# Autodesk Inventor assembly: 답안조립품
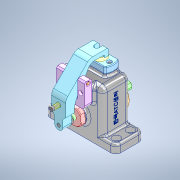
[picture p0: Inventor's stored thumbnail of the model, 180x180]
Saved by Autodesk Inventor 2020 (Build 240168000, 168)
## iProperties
Created: 2023-12
Part Number: 답안조립품
Document SubType Name: Assembly
Designer: oem
Author: oem
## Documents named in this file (14)
- C:\Users\oem\Desktop\731208V1015\답안조립품.iam
- C:\Users\oem\Desktop\731208V1015\본체.ipt
- C:\Users\oem\Desktop\731208V1015\가이드 부시.ipt
- C:\Users\oem\Desktop\731208V1015\조절 부시.ipt
- C:\Users\oem\Desktop\731208V1015\클램프 샤프트.ipt
- C:\Users\oem\Desktop\731208V1015\고정대.ipt
- C:\Users\oem\Desktop\731208V1015\육각 소켓 머리 볼트 M3 x 8.ipt
- C:\Users\oem\Desktop\731208V1015\가공품.ipt
- C:\Users\oem\Desktop\731208V1015\브라켓.ipt
- C:\Users\oem\Desktop\731208V1015\육각 소켓 머리 볼트 M3 x 30.ipt
- C:\Users\oem\Desktop\731208V1015\핀.ipt
- C:\Users\oem\Desktop\731208V1015\스프링.ipt
- C:\Users\oem\Desktop\731208V1015\클램프.ipt
- C:\Users\oem\Desktop\731208V1015\육각 머리 볼트 M6 x 12.ipt
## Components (4 placed, 4 different names)
1. 가이드 부시:1
2. 고정대:1
3. 가공품:1
4. 핀:1 — 플러쉬:1
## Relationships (1: Flush 1)
- 플러쉬:1 [Flush]: 핀:1
